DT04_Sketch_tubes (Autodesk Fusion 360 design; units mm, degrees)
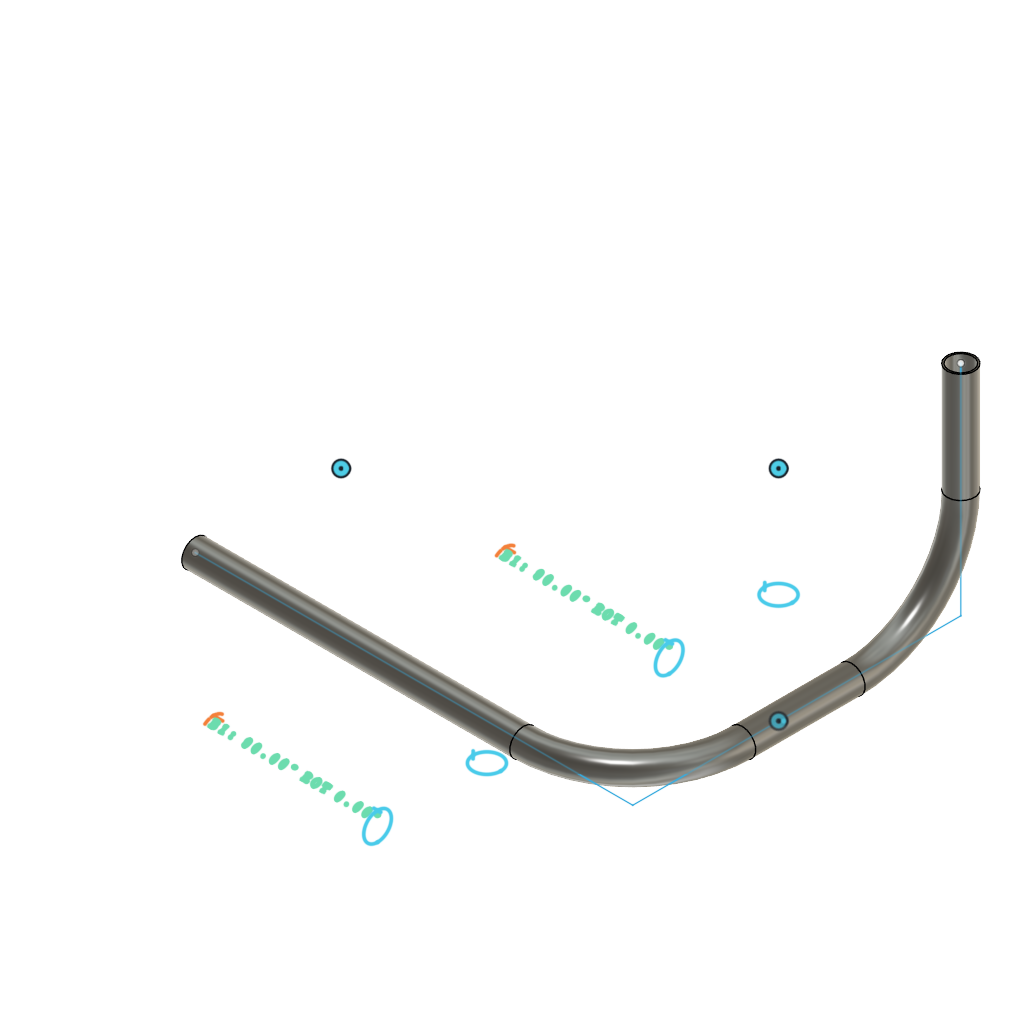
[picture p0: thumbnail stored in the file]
part number: 2026-10-26-12-17-31-515
parameter "OD_DEMO_ONLY_1_5_x_095_R6" = 38.1
parameter "Wall_DEMO_ONLY_1_5_x_095_R6" = 2.413
sketch "Tube points" plane through (0, 0, 0) normal (0, 0, 1) x axis (1, 0, 0)
sketch "TubePoints" plane through (0, 0, 0) normal (0, 0, 1) x axis (1, 0, 0)
work_plane "WorkPlane1" ExtraOffset 0
sketch "Sketch3" plane through (0, 203.2, 0) normal (1, 0, 0) x axis (0, 0, 1)
  circle C1 centre (0, 0) radius 19.05
  circle C2 centre (0, 0) radius 16.637
  dimension "d5" diameter C1 = 38.1 (= "OD_DEMO_ONLY_1_5_x_095_R6")
  dimension "d6" diameter C2 = 33.274 (= "OD_DEMO_ONLY_1_5_x_095_R6 - 2 * Wall_DEMO_ONLY_1_5_x_095_R6")
sweep "Sweep1" sketch "Sketch3" TwistAngle 0 TaperAngle 0 bodies "P1 Mirrored point tube"
sketch "TubePoints-m" plane through (0, 0, 0) normal (0, 0, 1) x axis (1, 0, 0)
work_plane "WorkPlane2" ExtraOffset 0
sketch "Sketch5" plane through (0, -203.2, 0) normal (1, 0, 0) x axis (0, 0, 1)
  circle C1 centre (0, 0) radius 19.05
  circle C2 centre (0, 0) radius 16.637
  dimension "d15" diameter C1 = 38.1 (= "OD_DEMO_ONLY_1_5_x_095_R6")
  dimension "d16" diameter C2 = 33.274 (= "OD_DEMO_ONLY_1_5_x_095_R6 - 2 * Wall_DEMO_ONLY_1_5_x_095_R6")
sweep "Sweep2" sketch "Sketch5" TwistAngle 0 TaperAngle 0 bodies "P2 Mirrored point tube"
sketch "3D practice frame" plane through (0, 0, 0) normal (0, 0, 1) x axis (1, 0, 0)
  line L1 (609.6, 0) -> (0, 0)
  line L2 (609.6, 457.2) -> (609.6, 0)
  line L3 (609.6, 457.2) -> (609.6, 457.2)
sketch "3D practice frame - tube paths" plane through (0, 0, 0) normal (0, 0, 1) x axis (1, 0, 0)
  line L1 (457.2, 0) -> (0, 0)
  line L2 (609.6, 304.8) -> (609.6, 152.4)
  line L3 (609.6, 457.2) -> (609.6, 457.2)
  arc A1 centre (457.2, 152.4) radius 152.4 clockwise from (609.6, 152.4) to (457.2, 0)
  arc A2 centre (609.6, 304.8) radius 152.4 between (609.6, 304.8) and (609.6, 457.2)
  tangent L1 A1
  tangent L2 A1
  tangent L2 A2
  tangent L3 A2
work_plane "WorkPlane3" ExtraOffset 0
sketch "Sketch8" plane through (0, 0, 0) normal (1, 0, 0) x axis (0, 0, 1)
  circle C1 centre (0, 0) radius 19.05
  circle C2 centre (0, 0) radius 16.637
  dimension "d25" diameter C1 = 38.1 (= "OD_DEMO_ONLY_1_5_x_095_R6")
  dimension "d26" diameter C2 = 33.274 (= "OD_DEMO_ONLY_1_5_x_095_R6 - 2 * Wall_DEMO_ONLY_1_5_x_095_R6")
sweep "Sweep3" sketch "Sketch8" TwistAngle 0 TaperAngle 0 bodies "Tube-01"
named bodies: "P1 Mirrored point tube", "P2 Mirrored point tube", "Tube-01"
